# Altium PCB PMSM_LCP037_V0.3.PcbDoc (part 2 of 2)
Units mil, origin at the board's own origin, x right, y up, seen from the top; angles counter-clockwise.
Board outline 6102.36 x 5157.48 mil, 2 copper layers (Top Layer, Bottom Layer); 134 components, 72 nets, 340 pads, 815 vias.
Unrouted connection lines stored in the file: 2.
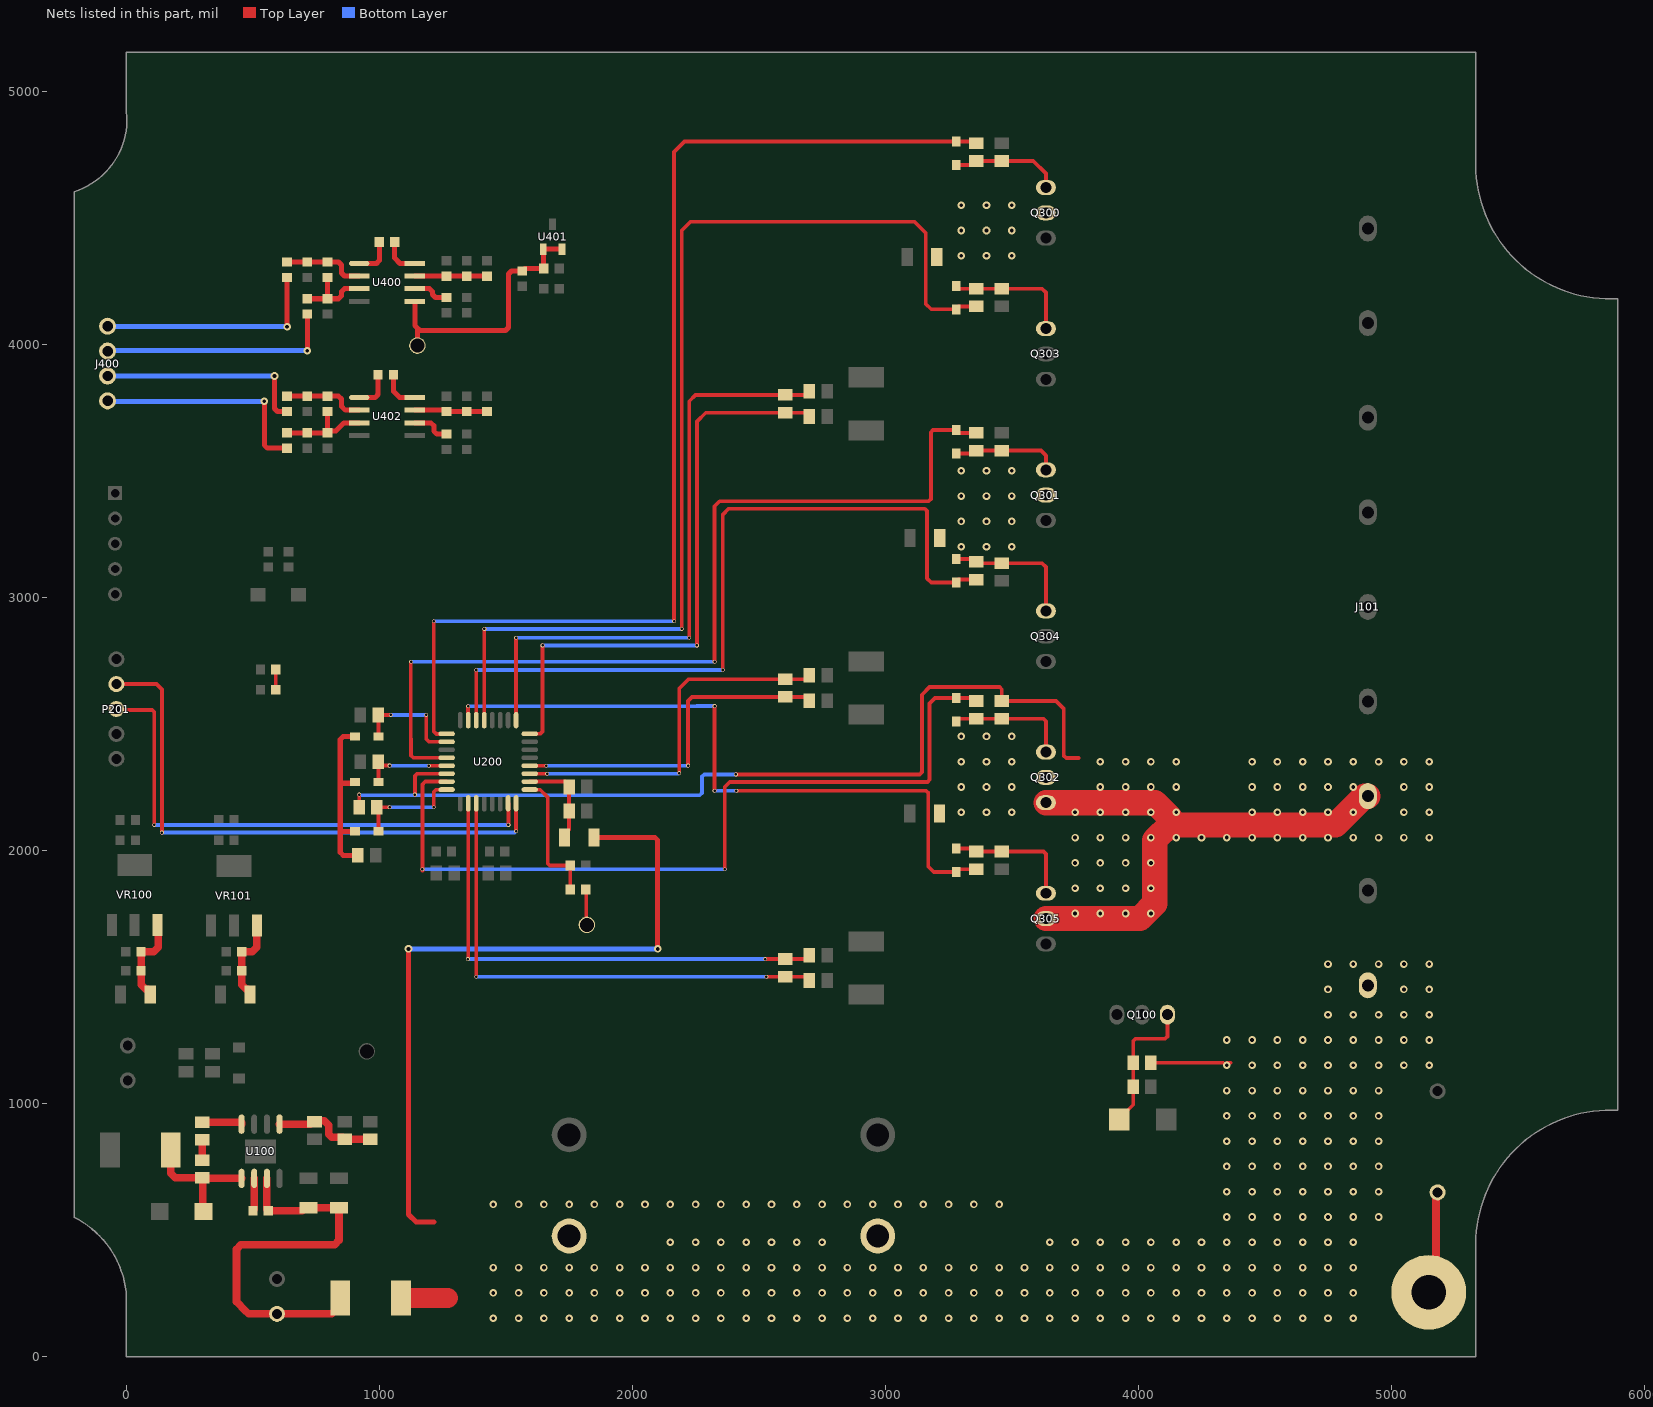
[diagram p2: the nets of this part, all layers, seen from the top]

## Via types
v1: diameter 30, hole 15, Top Layer to Bottom Layer, 713 vias
v2: diameter 15, hole 10, Top Layer to Bottom Layer, 65 vias
v3: diameter 20, hole 12, Top Layer to Bottom Layer, 33 vias
v4: diameter 24, hole 15, Top Layer to Bottom Layer, 4 vias

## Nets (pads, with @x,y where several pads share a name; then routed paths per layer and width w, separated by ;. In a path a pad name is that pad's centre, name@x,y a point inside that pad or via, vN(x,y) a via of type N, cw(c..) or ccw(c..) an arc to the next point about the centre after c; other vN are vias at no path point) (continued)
MOTOR-C: C205.1 J101.3 Q302.3 Q305.2 R304.1 U200.30 | length 5909.1
  Top Layer w15: C205.1@919.96,2170 C205.1@919.96,2170 v2(920,2220) ; v2(1140,2220) 1140,2293.97 1148.79,2302.76 U200.30@1265.63,2302.76 ; v2(2409.32,2300) 3136.21,2300 3145,2308.79 3145,2615 3175,2645 3451.21,2645 3460,2636.21 R304.1@3460,2590.08 3674.92,2590.08 3705,2560 3705,2375 3715,2365 3765,2365
  Top Layer w100: Q305.2@3635,1730 4006.42,1730 4065,1788.58 4065,2040 4125,2100 ; Q302.3@3635,2188 4066.42,2188 4125,2129.42 4125,2100 ; J101.3@4907.48,2214.05 4894.09,2214.05 4780.04,2100 4125,2100
  Bottom Layer w15: v2(920,2220) 922.5,2217.5 2266.21,2217.5 2275,2226.29 2275,2291.21 2283.79,2300 v2(2409.32,2300)
  other v1: 3750,1750 3850,1750 3950,1750 4050,1750 3750,1850 3850,1850 3950,1850 4050,1850 3750,1950 3850,1950 3950,1950 4050,1950 3750,2050 3850,2050 3950,2050 4050,2050 4150,2050 4250,2050 4350,2050 4450,2050 4550,2050 4650,2050 4750,2050 4850,2050 4950,2050 5050,2050 5150,2050 3750,2150 3850,2150 3950,2150 4050,2150 4150,2150 4450,2150 4550,2150 4650,2150 4750,2150 4850,2150 5050,2150 5150,2150 3850,2250 3950,2250 4050,2250 4150,2250 4450,2250 4550,2250 4650,2250 4750,2250 4850,2250 5050,2250 5150,2250 3850,2350 3950,2350 4050,2350 4150,2350 4450,2350 4550,2350 4650,2350 4750,2350 4850,2350 4950,2350 5050,2350 5150,2350
MPPT-I: J400.2 R403.1 | length 935.3
  Top Layer w20: v1(715,3975) R403.1@715,4119.69
  Bottom Layer w20: J400.2@-75,3973.42 -73.43,3975 v1(715,3975)
MPPT-POWER: J400.4 R406.2 | length 889.1
  Top Layer w20: v1(545,3775) 545,3601.4 556.72,3589.68 R406.2@635,3589.68
  Bottom Layer w20: J400.4@-75,3776.58 -73.43,3775 v1(545,3775)
NetC103_1: C103.1 R100.1 R103.2 U100.5 | length 414.1
  Top Layer w30: U100.5@605,917.11 726.75,917.11 739.65,930 782.43,930 800,912.43 800,877.57 812.26,865.31 855.47,865.31 R100.1@863.31,857.48 C103.1@963.31,857.48
NetC104_2: C104.2 C105.2 R105.2 VR100.3 | length 354.3
  Top Layer w30: R105.2@93.66,1430 93.66,1443.19 86.42,1450.43 75.37,1450.43 57.8,1468.01 C104.2@57.8,1523.31 C105.2@57.8,1598.31 107.43,1598.31 125,1615.88 125,1703.23 VR100.3@123.03,1705.2
NetC109_1: C109.1 D100.1 L100.1 U100.1 | length 513.9
  Top Layer w30: L100.1@175,815 175,722.53 192.57,704.96 C109.1@300,704.96 C109.1@301.03,703.93 ; D100.1@303.99,571.83 301.99,573.83 301.99,702.97 C109.1@301.03,703.93 ; U100.1@455,702.89 453.97,703.93 C109.1@301.03,703.93
NetC109_2: C109.2 R102.1 | length 79.9
  Top Layer w30: C109.2@300,775.04 R102.1@300,854.96
NetC110_1: C110.1 C111.2 C112.2 L101.2 R104.2 U100.3 | length 1643.3
  Top Layer w30: U100.3@555,702.89 555,581.3 560.32,575.98 R104.2@560.32,575 695.47,575 706.81,586.34 C112.2@720,586.34 C111.2@840,586.34 840,457.57 822.43,440 452.57,440 435,422.43 435,215 470.01,179.99 482.8,167.2 C110.1@595,167.2 811.73,167.2 845,200.47 L101.2@845,230
NetC116_2: C116.2 C117.2 R109.2 VR101.3 | length 340.3
  Top Layer w30: R109.2@488.66,1430 488.66,1443.19 481.42,1450.43 472.89,1450.43 455.32,1468.01 C116.2@455.32,1523.31 C117.2@455.32,1598.31 497.43,1598.31 515,1615.88 515,1701.34 VR101.3@515.55,1701.89
NetC400_1: C400.1 C402.2 R402.2 U400.2 | length 326.6
  Top Layer w20: R402.2@635,4325.32 C400.1@715,4325.32 C402.2@795,4325.32 838.28,4325.32 850,4313.6 850,4281.72 861.72,4270 U400.2@920,4270
NetC401_1: C401.1 R409.1 R412.1 U400.7 | length 285.1
  Top Layer w20: U400.7@1140,4270 1264.69,4270 C401.1@1265,4269.68 R412.1@1425,4269.69
NetC402_1: C402.1 C405.2 R403.2 U400.3 | length 315.3
  Top Layer w20: R403.2@715,4180.32 C405.2@795,4180.32 ; C402.1@795,4264.68 C405.2@795,4180.32 ; U400.3@920,4220 861.72,4220 850,4208.28 850,4192.03 838.28,4180.32 C405.2@795,4180.32
NetC407_1: C407.1 C409.2 R405.2 U402.2 | length 324.7
  Top Layer w20: R405.2@635,3795.32 C407.1@715,3795.32 C409.2@795,3795.32 838.28,3795.32 850,3783.6 850,3755 865,3740 U402.2@920,3740
NetC408_1: C408.1 R410.1 R413.1 U402.7 | length 287.2
  Top Layer w20: U402.7@1140,3740 1259.69,3740 C408.1@1265,3734.68 R413.1@1425,3734.69
NetC409_1: C409.1 C410.2 R406.1 R408.2 U402.3 | length 385.8
  Top Layer w20: R406.1@635,3650.31 R408.2@715,3650.32 C410.2@795,3650.32 ; C409.1@795,3734.68 C410.2@795,3650.32 ; U402.3@920,3690 860,3690 827.67,3657.67 802.35,3657.67 C410.2@795,3650.32
NetD101_A: D101.A R101.1 | length 80
  Top Layer w15: R101.1@590.31,2635 D101.A@590.32,2715
NetD103_2: D103.2 Q100.1 R106.1 R112.2 | length 562.9
  Top Layer w15: D103.2@3924.11,935 3924.11,937.85 3979.96,993.7 R112.2@3979.96,1065 R106.1@3979.96,1160 3979.96,1246.21 3988.75,1255 4106.21,1255 4115,1263.79 Q100.1@4115,1350
NetD200_1: D200.1 D201.1 D202.1 R203.2 | length 703.7
  Top Layer w20: D201.1@903.43,2270 898.43,2265 845,2265 ; D202.1@903.43,2450 856.72,2450 845,2438.28 845,2265 ; D200.1@903.54,2075 845,2075 ; R203.2@914.96,1980 856.72,1980 845,1991.72 845,2075 ; 845,2075 845,2265
NetD300_1: D300.1 Q301.1 R300.2 R303.2 | length 424
  Top Layer w15: D300.1@3280,3568.54 3348.58,3568.54 R300.2@3360,3579.96 R303.2@3460,3579.96 3615.04,3579.96 3635,3560 Q301.1@3635,3504
NetD301_1: D301.1 Q302.1 R301.2 R304.2 | length 487.4
  Top Layer w15: D301.1@3280,2508.58 3280,2511.16 3288.84,2520 R301.2@3360,2520 R304.2@3460,2520 3625,2520 3635,2510 Q302.1@3635,2388
NetD302_1: D302.1 Q304.1 R306.2 R309.2 | length 542
  Top Layer w15: D302.1@3280,3151.46 3348.58,3151.46 R306.2@3360,3140.04 3365,3135.04 R309.2@3460,3135.04 R309.2@3460,3135.04 3620,3135 3635,3120 Q304.1@3635,2946
NetD303_1: D303.1 Q300.1 R302.2 R305.2 | length 437.5
  Top Layer w15: D303.1@3280,4708.54 3337.48,4708.54 3353.9,4724.96 R302.2@3360,4724.96 R305.2@3460,4724.96 3585.04,4724.96 3635,4675 Q300.1@3635,4620
NetD304_1: D304.1 Q305.1 R307.2 R310.2 | length 518.9
  Top Layer w15: D304.1@3280,2006.46 3353.58,2006.46 3365,1995.04 R310.2@3460,1995.04 3624.96,1995.04 3635,1985 Q305.1@3635,1830
NetD307_1: D307.1 Q303.1 R308.2 R311.2 | length 510.5
  Top Layer w15: D307.1@3280,4231.46 3280,4228.88 3288.84,4220.04 R308.2@3360,4220.04 R311.2@3460,4220.04 R311.2@3460,4220.04 3620,4220 3635,4205 Q303.1@3635,4062
NetJ400_1: J400.1 R402.1 | length 905.5
  Top Layer w20: v1(635,4070) R402.1@635,4264.69
  Bottom Layer w20: J400.1@-75,4071.85 -73.15,4070 v1(635,4070)
NetJ400_3: J400.3 R405.1 | length 845
  Top Layer w20: v1(585,3875) 585,3746.4 596.72,3734.69 R405.1@635,3734.69
  Bottom Layer w20: J400.3@-75,3875 v1@586.54,3875
NetR102_2: R102.2 U100.8 | length 161.1
  Top Layer w30: R102.2@300,925.04 451.85,925.04 455,921.89 U100.8@455,917.11
NetR104_1: R104.1 U100.2 | length 121.6
  Top Layer w30: R104.1@505,581.3 U100.2@505,702.89
NetR200_1: R200.1 R201.2 U200.9 | length 532.5
  Top Layer w15: U200.9@1594.37,2239.76 1595.12,2239.02 1635.98,2239.02 1665,2210 1665,1948.79 1673.79,1940 R200.1@1754.69,1940 R201.2@1754.68,1845
NetR201_1: R201.1 T200.1 | length 141.9
  Top Layer w15: R201.1@1815.31,1845 1817.66,1842.66 1817.66,1707.34 T200.1@1820,1705
NetR400_1: R400.1 U400.1 | length 157.8
  Top Layer w20: U400.1@920,4320 987.97,4320 999.69,4331.72 R400.1@999.69,4405
NetR400_2: R400.2 U400.8 | length 152.1
  Top Layer w20: R400.2@1060.32,4405 1060.32,4341.4 1081.72,4320 U400.8@1140,4320
NetR404_1: R404.1 U400.6 | length 146.4
  Top Layer w20: U400.6@1140,4220 1198.28,4220 1210,4208.28 1210,4196.72 1221.72,4185 1264.69,4185 R404.1@1265,4185.31
NetR407_1: R407.1 U402.6 | length 156
  Top Layer w20: U402.6@1140,3690 1203.28,3690 1215,3678.28 1215,3657.03 1226.72,3645.31 R407.1@1265,3645.31
NetR411_1: R411.1 U402.1 | length 157.8
  Top Layer w20: U402.1@920,3790 982.97,3790 994.69,3801.72 R411.1@994.69,3880
NetR411_2: R411.2 U402.8 | length 160.2
  Top Layer w20: R411.2@1055.32,3880 1055.32,3814.68 1080,3790 U402.8@1140,3790
OPA0N: C303.1 R318.1 U200.16 | length 2355.4
  Top Layer w15: U200.16@1594.37,2460.24 1595.12,2460.98 1636.21,2460.98 1645,2469.77 v2(1645,2810) ; v2(2255,2810) 2255,3695 2289.96,3729.96 C303.1@2605,3729.96 2685,3729.96 R318.1@2699.96,3715
  Bottom Layer w15: v2(1645,2810) v2(2255,2810)
OPA0P: C303.2 R313.1 U200.17 | length 2437.3
  Top Layer w15: v2(1540,2840) 1540.24,2839.76 U200.17@1540.24,2514.37 ; v2(2225,2840) 2225,3775 2250,3800 2400,3800 2400.04,3800.04 C303.2@2605,3800.04 2685,3800.04 R313.1@2699.96,3815
  Bottom Layer w15: v2(1540,2840) v2(2225,2840)
OPA1N: C305.1 R320.1 U200.3 | length 2009
  Top Layer w15: v2(1382.77,1500) U200.3@1382.76,2185.63 ; v2(2530,1500) C305.1@2605,1499.96 C305.1@2605,1499.96 2685,1499.96 R320.1@2699.96,1485
  Bottom Layer w15: v2(1382.77,1500) v2(2530,1500)
OPA1P: C305.2 R315.1 U200.2 | length 1999.9
  Top Layer w15: v2(1350,1570) 1351.26,1571.26 U200.2@1351.26,2185.63 1350.51,2184.88 1350.51,2159.1 U200.2@1350,2158.58 ; v2(2525,1570) C305.2@2605,1570.04 C305.2@2605,1570.04 2685,1570.04 R315.1@2699.96,1585
  Bottom Layer w15: v2(1350,1570) v2(2525,1570)
OPA2N: C304.1 R319.1 U200.12 | length 1373.8
  Top Layer w15: U200.12@1594.37,2334.25 v2(1659.25,2334.25) ; v2(2220,2335) 2220,2590 2236.18,2606.18 C304.1@2605,2606.18 2685,2606.18 R319.1@2699.96,2591.22
  Bottom Layer w15: v2(1659.25,2334.25) 2219.25,2334.25 v2(2220,2335)
OPA2P: C304.2 R314.1 U200.11 | length 1462.7
  Top Layer w15: U200.11@1594.37,2302.76 v2(1662.76,2302.76) ; v2(2185,2305) 2185,2640 2221.26,2676.26 C304.2@2605,2676.26 2685,2676.26 R314.1@2699.96,2691.22
  Bottom Layer w15: v2(1662.76,2302.76) 2182.76,2302.76 v2(2185,2305)
PA0-DIO: P201.3 U200.7 | length 2087.4
  Top Layer w15: P201.3@-40,2558.43 -36.57,2555 101.21,2555 110,2546.21 v2(110,2100) ; U200.7@1508.74,2185.63 1510,2184.37 v2(1510,2100)
  Bottom Layer w15: v2(110,2100) v2(1510,2100)
PA1-CLK: P201.2 U200.8 | length 2267.2
  Top Layer w15: P201.2@-40,2656.85 118.15,2656.85 140,2635 v2(140,2070) ; v2@1540,2075 v2(1540.24,2075.24) U200.8@1540.24,2185.63
  Bottom Layer w15: v2(140,2070) 1535,2070 v2(1540.24,2075.24)
PE: C115.2 T101.6 | length 409.5
  Top Layer w30: T101.6@5148.31,252.52 5176.99,281.21 5176.99,641.21 C115.2@5183.31,647.52
POWER: C300.2 C301.2 C302.2 C310.1 C311.1 J101.1 L101.1 Q300.2 Q301.2 Q302.2 R106.2 R107.2 | length 3337
  Top Layer w15: R106.2@4050.04,1160 4335.94,1160 4345.94,1150 v1(4350,1150) ; v1@4350,1160 4365,1160
  Top Layer w20: v1(1115,1610) 1115,560 1145,530 1215,530 ; R107.2@1848.66,2050 2090,2050 2100,2040 v1(2100,1610)
  Top Layer w80: L101.1@1085,230 1270,230
  Bottom Layer w20: v1(1115,1610) v1(2100,1610)
  other v1: 1450,150 1550,150 1650,150 1750,150 1850,150 1950,150 2050,150 2150,150 2250,150 2350,150 2450,150 2550,150 2650,150 2750,150 2850,150 2950,150 3050,150 3150,150 3250,150 3350,150 3450,150 3550,150 3650,150 3750,150 3850,150 3950,150 4050,150 4150,150 4250,150 4350,150 4450,150 4550,150 4650,150 4750,150 4850,150 1450,250 1550,250 1650,250 1750,250 1850,250 1950,250 2050,250 2150,250 2250,250 2350,250 2450,250 2550,250 2650,250 2750,250 2850,250 2950,250 3050,250 3150,250 3250,250 3350,250 3450,250 3550,250 3650,250 3750,250 3850,250 3950,250 4050,250 4150,250 4250,250 4350,250 4450,250 4550,250 4650,250 4750,250 4850,250 1450,350 1550,350 1650,350 1750,350 1850,350 1950,350 2050,350 2150,350 2250,350 2350,350 2450,350 2550,350 2650,350 2750,350 2850,350 2950,350 3050,350 3150,350 3250,350 3350,350 3450,350 3550,350 3650,350 3750,350 3850,350 3950,350 4050,350 4150,350 4250,350 4350,350 4450,350 4550,350 4650,350 4750,350 4850,350 2150,450 2250,450 2350,450 2450,450 2550,450 2650,450 2750,450 3650,450 3750,450 3850,450 3950,450 4050,450 4150,450 4250,450 4250,450 4350,450 4450,450 4550,450 4650,450 4750,450 4850,450 4350,550 4450,550 4550,550 4650,550 4750,550 4850,550 4950,550 1450,600 1550,600 1650,600 1750,600 1850,600 1950,600 2050,600 2150,600 2250,600 2350,600 2450,600 2550,600 2650,600 2750,600 2850,600 2950,600 3050,600 3150,600 3250,600 3350,600 3450,600 4350,650 4450,650 4550,650 4650,650 4750,650 4850,650 4950,650 4350,750 4450,750 4550,750 4650,750 4750,750 4850,750 4950,750 4350,850 4450,850 4550,850 4650,850 4750,850 4850,850 4950,850 4350,950 4450,950 4550,950 4650,950 4750,950 4850,950 4950,950 4350,1050 4450,1050 4550,1050 4650,1050 4750,1050 4850,1050 4950,1050 4450,1150 4550,1150 4650,1150 4750,1150 4850,1150 4950,1150 5050,1150 5150,1150 4350,1250 4450,1250 4550,1250 4650,1250 4750,1250 4850,1250 4950,1250 5050,1250 5150,1250 4750,1350 4850,1350 4950,1350 5050,1350 5150,1350 4750,1450 5050,1450 5150,1450 4750,1550 4850,1550 4950,1550 5050,1550 5150,1550 3300,2150 3400,2150 3500,2150 3300,2250 3400,2250 3500,2250 3300,2350 3400,2350 3500,2350 3300,2450 3400,2450 3500,2450 3300,3200 3400,3200 3500,3200 3300,3300 3400,3300 3500,3300 3300,3400 3400,3400 3500,3400 3300,3500 3400,3500 3500,3500 3300,4350 3400,4350 3500,4350 3300,4450 3400,4450 3500,4450 3300,4550 3400,4550 3500,4550
UH: D303.2 R302.1 U200.25 | length 4509.7
  Top Layer w15: v2(1215,2905) 1215,2470 1225,2460 1265.39,2460 U200.25@1265.63,2460.24 ; v2(2165,2905) 2165,4760 2206.46,4801.46 D303.2@3280,4801.46 3353.58,4801.46 R302.1@3360,4795.04
  Bottom Layer w15: v2(1215,2905) v2(2165,2905)
UL: D307.2 R308.1 U200.21 | length 4209.2
  Top Layer w15: U200.21@1414.25,2514.37 1414.25,2874.25 v2(1415,2875) ; v2(2195,2875) 2195,4450 2230,4485 3115,4485 3160,4440 3160,4160 3181.46,4138.54 D307.2@3280,4138.54 3280,4141.12 3288.84,4149.96 R308.1@3360,4149.96
  Bottom Layer w15: v2(1415,2875) v2(2195,2875)
VB-U: C205.2 D200.2 U200.32 | length 437.4
  Top Layer w15: D200.2@996.46,2075 996.46,2163.58 C205.2@990.04,2170 v2(1040,2170) ; v2(1215,2170) 1215,2230.23 1223.79,2239.02 1264.88,2239.02 U200.32@1265.63,2239.76
  Bottom Layer w15: v2(1040,2170) v2(1215,2170)
VB-V: C206.2 D201.2 U200.29 | length 355.8
  Top Layer w15: C206.2@994.92,2350 C206.2@996.34,2348.58 ; D201.2@996.34,2270 C206.2@996.34,2348.58 ; v2(1040,2335) 1009.92,2335 C206.2@996.34,2348.58 ; v2(1195.75,2334.25) U200.29@1265.63,2334.25
  Bottom Layer w15: v2(1040,2335) 1040.75,2334.25 v2(1195.75,2334.25)
VB-W: C207.2 D202.2 U200.26 | length 456
  Top Layer w15: D202.2@996.34,2450 996.34,2533.58 C207.2@994.92,2535 v2(1045,2535) ; v2(1185,2535) 1185,2440 1190.01,2434.99 1196.26,2428.74 U200.26@1265.63,2428.74
  Bottom Layer w15: v2(1045,2535) v2(1185,2535)
VCC1.25REF: C404.2 R401.2 T400.1 U400.5 U401.1 U401.3 | length 1061.3
  Top Layer w20: U400.5@1140,4170 1140,4075 1150,4065 ; T400.1@1150,3995 1150,4065 ; U401.3@1722.4,4376.6 U401.1@1647.6,4376.6 1648.8,4375.4 1648.8,4301.2 R401.2@1650,4300 1575.67,4300 1565.98,4290.32 1521.72,4290.32 1510,4278.6 1510,4066.72 1498.28,4055 1160,4055 1150,4065
Vdect: C108.2 R107.1 R108.2 U200.10 | length 375.6
  Top Layer w15: U200.10@1594.37,2271.26 1734.63,2271.26 1749.96,2255.93 C108.2@1749.96,2250 R108.2@1749.96,2155 1749.96,2081.81 1731.34,2063.19 R107.1@1731.34,2050
VH: D300.2 R300.1 U200.28 | length 3650.9
  Top Layer w15: v2@1123.84,2745 1123.84,2441.16 1125,2440 1125,2374.53 1133.79,2365.75 U200.28@1265.63,2365.75 ; v2(2325,2745) 2325,3360 2345,3380 3171.21,3380 3180,3388.79 3180,3652.67 3188.79,3661.46 D300.2@3280,3661.46 3280,3658.88 3288.84,3650.04 R300.1@3360,3650.04
  Bottom Layer w15: v2(1125,2745) v2(2325,2745)
VL: D302.2 R306.1 U200.22 | length 3083.2
  Top Layer w15: v2(1382.39,2712.61) 1382.76,2712.24 U200.22@1382.76,2514.37 ; v2(2357.61,2712.61) 2357.61,3327.61 2380,3350 3156.21,3350 3165,3341.21 3165,3075 3181.46,3058.54 D302.2@3280,3058.54 3280,3061.12 3288.84,3069.96 R306.1@3360,3069.96
  Bottom Layer w15: v2(1382.39,2712.61) v2(2357.61,2712.61)
WH: D301.2 R301.1 U200.31 | length 3282.6
  Top Layer w15: v2@1170,1920 v2(1170,1925) 1170,2260 1181.26,2271.26 U200.31@1265.63,2271.26 ; v2(2365,1925) 2365,2250 2385,2270 3166.21,2270 3175,2278.79 3175,2580 3196.5,2601.5 D301.2@3280,2601.5 3348.58,2601.5 R301.1@3360,2590.08
  Bottom Layer w15: v2(1170,1925) v2@2365.55,1925
WL: D304.2 R307.1 U200.23 | length 2709.8
  Top Layer w15: v2(1350.65,2569.35) 1350.65,2514.98 U200.23@1351.26,2514.37 ; v2(2325,2235) v2(2325,2570) ; v2(2411.37,2235) 3161.21,2235 3170,2226.21 3170,1935 3191.46,1913.54 D304.2@3280,1913.54 3280,1916.12 3288.84,1924.96 R307.1@3360,1924.96
  Bottom Layer w15: v2(1350.65,2569.35) 2255,2569.35 2255.65,2570 v2(2325,2570) ; v2(2325,2235) v2(2411.37,2235)
pads on no net: J101.6 J101.7 J101.8 J101.9 P201.1 U100.6 U100.7 U100.9 U200.13
copper on no net:
  other v4: 510.32,790.31 549.69,790.31 510.32,829.68 549.69,829.68

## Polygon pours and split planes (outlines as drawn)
DGND on Bottom Layer "NONET_L02_P-001" (solid, remove dead copper, pour order 42): 2010,3260 2070,3200 2070,1670 2035,1635 700,1635 680,1655 680,2775 625,2830 445,2830 405,2870 405,3230 435,3260
GND on Bottom Layer "NONET_L02_P-001" (solid, remove dead copper, pour order 46): 4075,1277.94 3967.06,1277.94 3960,1285 3960,1490 3945,1505 3790,1505 3775,1520 3775,1645 3785,1655 4205,1655 4240,1690 4240,1920 4255,1935 5185,1935 5210,1910 5210,1680 5190,1660 4645,1660 4625,1640 4625,1430 4610,1415 4095,1415 4075,1395 4075,1295 4060,1280
DGND on Bottom Layer "DGND_L02_P044" (solid, remove dead copper, pour order 44): 970,1000 1050,920 1050,85 1015,50 440,50 420,70 420,415 350,485 40,485 -130,655 -130,975 -105,1000
DGND on Bottom Layer "NONET_L02_P-001" (solid, remove dead copper, pour order 40): 210,3535 265,3480 1885,3480 1990,3585 1990,4555 1915,4630 240,4630 210,4600
DGND on Bottom Layer "NONET_L02_P-001" (solid, remove dead copper, pour order 27): 1165,765 1200,730 2050,730 3025,730 3105,810 3105,1435 3060,1480 1225,1480 1165,1420
ISENCE on Bottom Layer "NONET_L02_P-001" (solid, remove dead copper, pour order 13): 2470,1600 2445,1625 2445,4105 2470,4130 3140,4130 3155,4115 3155,1630 3125,1600
POWER on Bottom Layer "NONET_L02_P-001" (solid, remove dead copper, pour order 10): 5185,1620 5210,1595 5210,1145 5200,1135 5080,1135 5065,1120 5065,490 5015,440 4905,440 4890,425 4890,70 1200,70 1175,95 1175,645 1210,680 4275,680 4305,710 4305,1345 4320,1360 4645,1360 4675,1390 4675,1600 4695,1620
POWER on Bottom Layer "NONET_L02_P-001" (solid, remove dead copper, pour order 6): 3700,4575 3190,4575 3180,4565 3180,565 3730,565 3730,4545
MOTOR-C on Bottom Layer "NONET_L02_P-001" (solid, remove dead copper, pour order 5): 3575,2240 3728.95,2240 3750,2261.05 3750,2380 3775,2405 5150,2405 5205,2350 5205,1980 5190,1965 4205,1965 4170,1930 4170,1700 4140,1670 3595,1670 3575,1690 3575,1780 3585,1790 3700,1790 3715,1805 3715,2075 3695,2095 3575,2095 3565,2105 3565,2230
MOTOR-B on Bottom Layer "NONET_L02_P-001" (solid, remove dead copper, pour order 3): 4127.45,3350 4149.14,3328.32 4149.14,2775.86 4170,2755 5190.53,2755 5221.3,2724.23 5221.3,2446.3 5205,2430 3770,2430 3725,2475 3725,2780 3715,2790 3585,2790 3575,2800 3575,2890 3585,2900 3700,2900 3705,2905 3705,3165 3690,3180 3590,3180 3575,3195 3575,3340 3585,3350
MOTOR-A on Bottom Layer "NONET_L02_P-001" (solid, remove dead copper, pour order 0): 4690,4465 4745,4410 4745,3205 4785,3165 5170,3165 5220,3115 5220,2790 5205,2775 4225,2775 4175,2825 4175,3595 4150,3620 3745,3620 3720,3645 3720,3895 3710,3905 3570,3905 3560,3915 3560,4000 3575,4015 3695,4015 3715,4035 3715,4340 3705,4350 3570,4350 3560,4360 3560,4455 3570,4465
DGND on Top Layer "NONET_L02_P-001" (solid, remove dead copper, pour order 41): 2010,3260 2070,3200 2070,1670 2035,1635 700,1635 680,1655 680,2775 625,2830 450,2830 405,2875 405,3225 440,3260
GND on Top Layer "NONET_L02_P-001" (solid, remove dead copper, pour order 45): 4075,1277.94 3967.06,1277.94 3960,1285 3960,1490 3945,1505 3790,1505 3775,1520 3775,1645 3785,1655 4205,1655 4240,1690 4240,1920 4255,1935 5185,1935 5210,1910 5210,1680 5190,1660 4645,1660 4625,1640 4625,1430 4610,1415 4095,1415 4075,1395 4075,1295 4060,1280
DGND on Top Layer "DGND_L01_P043" (solid, remove dead copper, pour order 43): 970,1000 1050,920 1050,85 1015,50 440,50 420,70 420,415 350,485 40,485 -130,655 -130,975 -105,1000
DGND on Top Layer "NONET_L02_P-001" (solid, remove dead copper, pour order 39): 210,3535 265,3480 1885,3480 1990,3585 1990,4555 1915,4630 240,4630 210,4600
ISENCE on Top Layer "NONET_L02_P-001" (solid, remove dead copper, pour order 38): 2815,1600 2810,1605 2810,1625 2800,1635 2460,1635 2445,1650 2445,2170 2475,2200 3115,2200 3120,2195 3120,2090 3126.3,2083.7 3146.3,2083.7 3155,2075 3155,1900 3170,1885 3545,1885 3560,1870 3560,1680 3580,1660 3715,1660 3730,1645 3730,1410 3715,1395 3100,1395 3080,1415 3080,1585 3065,1600
IU on Top Layer "NONET_L02_P-001" (solid, remove dead copper, pour order 37): 3110,4105 2445,4105 2445,4410 2470,4435 3090,4435 3110,4415
IU on Top Layer "NONET_L02_P-001" (solid, remove dead copper, pour order 36): 2815,3830 2810,3835 2810,3860 2805,3865 2455,3865 2445,3875 2445,4105 2470,4130 3140,4130 3155,4115 3155,4085 3165,4075 3535,4075 3550,4060 3550,3910 3560,3900 3700,3900 3710,3890 3710,3720 3695,3705 3015,3705 2995,3725 2995,3830
ISENCE on Top Layer "NONET_L02_P-001" (solid, remove dead copper, pour order 35): 2995,2575 2995,2645 3005,2655 3145,2655 3155,2645 3155,2340 3135,2320 2455,2320 2445,2330 2445,2565 2455,2575
IV on Top Layer "NONET_L02_P-001" (solid, remove dead copper, pour order 33): 2855,2705 2465,2705 2445,2725 2445,3305 2465,3325 3110,3325 3120,3315 3120,3025 3135,3010 3525,3010 3535,3000 3535,2790 3545,2780 3700,2780 3715,2765 3715,2625 3705,2615 3515,2615 3505,2625 3505,2655 3495,2665 3002.5,2665 2995,2680 2995,2685 2995,2705
ISENCE on Top Layer "NONET_L02_P-001" (solid, remove dead copper, pour order 32): 2995,3700 3120,3700 3130,3690 3130,3430 3120,3420 2460,3420 2445,3435 2445,3680 2465,3700
POWER on Top Layer "NONET_L02_P-001" (solid, remove dead copper, pour order 31): 3730,2313 3700,2343 3577,2343 3560,2360 3560,2465 3550,2475 3190,2475 3175,2460 3175,2060 3195,2040 3525,2040 3550,2065 3550,2229.42 3567.79,2247.21 3719.21,2247.21 3730,2258
POWER on Top Layer "NONET_L02_P-001" (solid, remove dead copper, pour order 30): 3575,4575 3570,4580 3570,4665 3555,4680 3190,4680 3180,4670 3180,4275 3190,4265 3530,4265 3550,4285 3550,4460 3565.2,4475.2 3715.2,4475.2 3730,4490 3730,4565 3720,4575
POWER on Top Layer "NONET_L02_P-001" (solid, remove dead copper, pour order 29): 3730,3450 3720,3460 3575,3460 3565,3470 3565,3530 3555,3540 3185,3540 3180,3535 3180,3190 3190,3180 3555,3180 3565,3190 3565,3343.53 3580.47,3359 3715,3359 3730,3374
DGND on Top Layer "NONET_L02_P-001" (solid, remove dead copper, pour order 26): 2810,1470 2805,1465 2805,1435 2795,1425 1173.33,1425 1165,1400 1165,765.97 1200.97,730 3890,730 3950,790 3950,1400 3880,1470 2995,1470
no net on Top Layer "NONET_L02_P-001" (solid, pour order 25): 2805,4430
POWER on Top Layer "NONET_L02_P-001" (solid, remove dead copper, pour order 21): 3190,4575 3180,4565 3180,4275 3190,4265 3530,4265 3550,4285 3550,4460 3565,4475 3715,4475 3730,4490 3730,4545 3700,4575
no net on Top Layer "NONET_L02_P-001" (solid, pour order 17): 2825,3755
no net on Top Layer "NONET_L02_P-001" (solid, pour order 15): 2825,3770
no net on Top Layer "NONET_L02_P-001" (solid, pour order 12): 3730,4475
POWER on Top Layer "NONET_L02_P-001" (solid, remove dead copper, pour order 9): 5185,1620 5210,1595 5210,1145 5200,1135 5080,1135 5065,1120 5065,490 5015,440 4905,440 4890,425 4890,70 1200,70 1175,95 1175,645 1210,680 4275,680 4305,710 4305,1345 4320,1360 4645,1360 4675,1390 4675,1600 4695,1620
MOTOR-C on Top Layer "NONET_L02_P-001" (solid, remove dead copper, pour order 4): 3575,2240 3728.95,2240 3750,2261.05 3750,2380 3775,2405 5150,2405 5205,2350 5205,1980 5190,1965 4205,1965 4170,1930 4170,1700 4140,1670 3595,1670 3575,1690 3575,1780 3585,1790 3700,1790 3715,1805 3715,2075 3695,2095 3575,2095 3565,2105 3565,2230
MOTOR-B on Top Layer "NONET_L02_P-001" (solid, remove dead copper, pour order 2): 4127.45,3350 4149.14,3328.32 4149.14,2775.86 4170,2755 5190.53,2755 5221.3,2724.23 5221.3,2446.3 5205,2430 3770,2430 3725,2475 3725,2780 3715,2790 3585,2790 3575,2800 3575,2890 3585,2900 3700,2900 3705,2905 3705,3165 3690,3180 3590,3180 3575,3195 3575,3340 3585,3350
MOTOR-A on Top Layer "NONET_L02_P-001" (solid, remove dead copper, pour order 1): 4690,4465 4745,4410 4745,3205 4785,3165 5170,3165 5220,3115 5220,2790 5205,2775 4225,2775 4175,2825 4175,3595 4150,3620 3745,3620 3720,3645 3720,3895 3710,3905 3570,3905 3560,3915 3560,4000 3575,4015 3695,4015 3715,4035 3715,4340 3705,4350 3570,4350 3560,4360 3560,4455 3570,4465

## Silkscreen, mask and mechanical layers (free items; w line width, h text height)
Top Overlay:
  circle w10: c187.01,4899.09 r157.48
  circle w10: c5147.64,4899.09 r157.48
  circle w10: c187.01,253.43 r157.48
  circle w10: c5147.64,253.43 r157.48
  lines w10: -135,2915 -135,3510
  text "光伏水泵控制LCP037" at 650,4959.16 h150
  text "2023-6-13-V0.3" at 649.89,4816.33 h120
  text "MPPT" at -145,4275 h80
  text "1.25V" at 940,4055.89 h80
  text "GD1" at 90,4050.89 h80
  text "I" at 110,3950 h80
  text "GD2" at 95,3845.89 h80
  text "V" at 95.07,3730 h80
  text "下载口" at 0,3536.96 h80
  text "5V" at 125,3390.89 h80
  text "DG" at 125,3290.89 h80
  text "复位" at 790,2961.96 h80
  text "U" at 5273.62,2885.57 h200
  text "5V指示" at 656.73,2785 h80 r270
  text "数码管" at 75,2737.25 h80
  text "CLK_PA1" at 118.11,2615.74 h80
  text "DIO_PA0" at 118.11,2537 h80
  text "V" at 5269.87,2489.65 h200
  text "GD" at 118.11,2444.94 h80
  text "5V" at 118.11,2326.83 h80
  text "W" at 5253.94,2131.38 h200
  text "-" at 5293.31,1746.84 h300
  text "+" at 5281.5,1398.05 h200
  text "12V" at 885,1105 h80
  text "外壳" at 5088.67,25.37 h90
Top Solder:
  drawing of 168 lines, arcs and shapes, not listed
Bottom Solder:
  lines w59.06: 1240,145 1377.8,145 ; 1245,295 1382.8,295 ; 1250,435 1387.8,435 ; 1250,930 1387.8,930 ; 1250,1330 1387.8,1330 ; 1255,1105 1392.8,1105 ; 1561,145 1698.8,145 ; 1565,295 1702.8,295 ; 1565,1330 1702.8,1330 ; 1570,1110 1707.8,1110 ; 1882,145 2019.8,145 ; 1885,295 2022.8,295 ; 1955,1300 2092.8,1300 ; 1977.76,1106.05 2115.56,1106.05 ; 2060,435 2197.8,435 ; 2203,145 2340.8,145 ; 2205,295 2342.8,295 ; 2365,435 2502.8,435 ; 2380,1320 2517.8,1320 ; 2405,1100 2542.8,1100 ; 2495,3625 2632.8,3625 ; 2524,145 2661.8,145 ; 2525,295 2662.8,295 ; 2557.2,2000 2695,2000 ; 2567.2,1815 2705,1815 ; 2567.2,2405 2705,2405 ; 2610,3545 2747.8,3545 ; 2655,435 2792.8,435 ; 2837.2,1815 2975,1815 ; 2842.2,1990 2980,1990 ; 2845,145 2982.8,145 ; 2845,295 2982.8,295 ; 2852.2,2400 2990,2400 ; 2855,3540 2992.8,3540 ; 3105,1657.2 3105,1795 ; 3110,595 3247.8,595 ; 3110,2750 3110,2887.8 ; 3165,295 3302.8,295 ; 3166,145 3303.8,145 ; 3400,435 3537.8,435 ; 3485,295 3622.8,295 ; 3487,145 3624.8,145 ; 3580,620 3717.8,620 ; 3750,435 3887.8,435 ; 3760,3245 3897.8,3245 ; 3765,3115 3902.8,3115 ; 3770,2700 3907.8,2700 ; 3770,2900 3907.8,2900 ; 3770,3000 3907.8,3000 ; 3775,2790 3912.8,2790 ; 3790,2605 3927.8,2605 ; 3790,3795 3927.8,3795 ; 3790,3898.33 3927.8,3898.33 ; 3790,4001.67 3927.8,4001.67 ; 3790,4105 3927.8,4105 ; 3790,4208.33 3927.8,4208.33 ; 3790,4311.67 3927.8,4311.67 ; 3790,4415 3927.8,4415 ; 3795,2515 3932.8,2515 ; 3805,295 3942.8,295 ; 3808,145 3945.8,145 ; 3825,2290 3962.8,2290 ; 3830,2180 3967.8,2180 ; 3835,1910 3972.8,1910 ; 3845,1785 3982.8,1785 ; 3850,2060 3987.8,2060 ; 3900,3700 4037.8,3700 ; 3922.2,1570 4060,1570 ; 4015,3800 4152.8,3800 ; 4015,3901.67 4152.8,3901.67 ; 4015,4003.33 4152.8,4003.33 ; 4015,4105 4152.8,4105 ; 4015,4206.67 4152.8,4206.67 ; 4015,4308.33 4152.8,4308.33 ; 4015,4410 4152.8,4410 ; 4055,3090 4055,3227.8 ; 4060,2565 4060,2702.8 ; 4060,2825 4060,2962.8 ; 4090,2145 4090,2282.8 ; 4095,1765 4095,1902.8 ; 4105,435 4242.8,435 ; 4125,295 4262.8,295 ; 4129,145 4266.8,145 ; 4160,3700 4297.8,3700 ; 4237.2,1550 4375,1550 ; 4245,2100 4382.8,2100 ; 4245,3200 4382.8,3200 ; 4250,3095 4387.8,3095 ; 4260,2655 4397.8,2655 ; 4260,3600 4397.8,3600 ; 4280,2540 4417.8,2540 ; 4300,3800 4437.8,3800 ; 4300,4200 4437.8,4200 ; 4300,4300 4437.8,4300 ; 4415,145 4552.8,145 ; 4415,295 4552.8,295 ; 4415,435 4552.8,435 ; 4415,570 4552.8,570 ; 4415,685 4552.8,685 ; 4415,820 4552.8,820 ; 4415,970 4552.8,970 ; 4415,1105 4552.8,1105 ; 4415,1255 4552.8,1255 ; 4445,3700 4582.8,3700 ; 4470,1720 4470,1857.8 ; 4485,3500 4622.8,3500 ; 4490,3405 4627.8,3405 ; 4500,3290 4637.8,3290 ; 4530,3190 4667.8,3190 ; 4545,2285 4682.8,2285 ; 4550,2185 4687.8,2185 ; 4550,3090 4687.8,3090 ; 4550,3800 4687.8,3800 ; 4555,3595 4692.8,3595 ; 4555,3995 4692.8,3995 ; 4555,4100 4692.8,4100 ; 4560,2085 4697.8,2085 ; 4560,2645 4697.8,2645 ; 4560,2950 4697.8,2950 ; 4560,3900 4697.8,3900 ; 4560,4300 4697.8,4300 ; 4565,4200 4702.8,4200 ; 4570,2540 4707.8,2540 ; 4575,1855 4712.8,1855 ; 4580,1730 4717.8,1730 ; 4725,570 4862.8,570 ; 4725,705 4862.8,705 ; 4725,810 4862.8,810 ; 4725,965 4862.8,965 ; 4725,1105 4862.8,1105 ; 4725,1270 4862.8,1270 ; 4755,2840 4892.8,2840 ; 4790,295 4790,432.8 ; 4850,3105 4987.8,3105 ; 5032.2,1275 5170,1275 ; 5035,2950 5172.8,2950 ; 5060,2135 5060,2272.8 ; 5060,2540 5060,2677.8 ; 5065,1720 5065,1857.8 ; 5110,1382.2 5110,1520
Mechanical 1:
  circle w10: c187.72,252.99 r68.9
  circle w10: c187.72,4897.68 r68.9
  circle w10: c5147.64,4899.09 r68.9
  lines w10: -206.69,548.7 cw(c-374.92,213) 0,233.74 0,-2.48 5334.65,-2.48 5334.65,469.96 cw(c5866.14,440.43) 5895.67,971.93 5895.67,4180.59 cw(c5866.14,4712.09) 5334.65,4682.56 5334.65,5155 0,5155 0,4918.78 cw(c-297.17,4888.49) -206.69,4603.82 -206.69,2576.26 -206.69,548.7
